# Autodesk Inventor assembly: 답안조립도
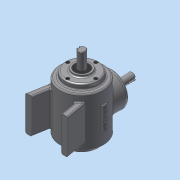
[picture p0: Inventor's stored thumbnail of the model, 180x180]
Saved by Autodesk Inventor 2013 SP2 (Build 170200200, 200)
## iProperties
Created: 2015-01
Part Number: 답안조립도
Document SubType Name: Assembly
Designer: dgall
Author: dgall
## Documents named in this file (15)
- C:\Documents and Settings\dgall\바탕 화면\450105V1026\답안조립도.iam
- C:\Documents and Settings\dgall\바탕 화면\450105V1026\본체.ipt
- C:\Documents and Settings\dgall\바탕 화면\450105V1026\커버2.ipt
- C:\Documents and Settings\dgall\바탕 화면\450105V1026\커버.ipt
- C:\Documents and Settings\dgall\바탕 화면\450105V1026\베어링 6203.ipt
- C:\Documents and Settings\dgall\바탕 화면\450105V1026\오일실.ipt
- C:\Documents and Settings\dgall\바탕 화면\450105V1026\서브 축.ipt
- 서브 축.ipt
- C:\Documents and Settings\dgall\바탕 화면\450105V1026\서브 베벨기어.ipt
- C:\Documents and Settings\dgall\바탕 화면\450105V1026\키 4x4.ipt
- C:\Documents and Settings\dgall\바탕 화면\450105V1026\키 5x5.ipt
- C:\Documents and Settings\dgall\바탕 화면\450105V1026\메인 베벨기어.ipt
- C:\Documents and Settings\dgall\바탕 화면\450105V1026\메인 축.ipt
- 메인 축.ipt
- C:\Documents and Settings\dgall\바탕 화면\450105V1026\M4.ipt
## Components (12 placed, 1 different names)
1. M4:1
2. M4:2
3. M4:3
4. M4:4
5. M4:5
6. M4:6
7. M4:7
8. M4:8
9. M4:9
10. M4:10
11. M4:11
12. M4:12
